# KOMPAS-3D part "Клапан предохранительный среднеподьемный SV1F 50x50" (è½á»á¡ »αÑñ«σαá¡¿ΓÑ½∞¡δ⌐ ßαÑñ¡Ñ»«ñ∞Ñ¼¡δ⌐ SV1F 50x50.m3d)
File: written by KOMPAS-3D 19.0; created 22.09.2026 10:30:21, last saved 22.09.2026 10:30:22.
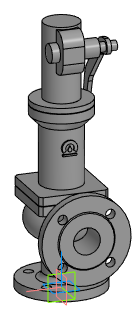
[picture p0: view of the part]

Document properties: Автор: Евгений; Полное имя файла: Z:\3.Личные\sachek\Dendor\_3D для проектировщиков\5.8 SV1F. Клапан предохранительный среднеподьемный\SV1F_STP\Клапан предохранительный среднеподьемный SV1F 50x50.m3d

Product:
- Part/product: Клапан предохранительный среднеподьемный SV1F 50x50
    Масса: 29.8416

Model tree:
1. Операция без истории:1  (labels: Клапан предохранительный среднеподьемный SV1F 50x50)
